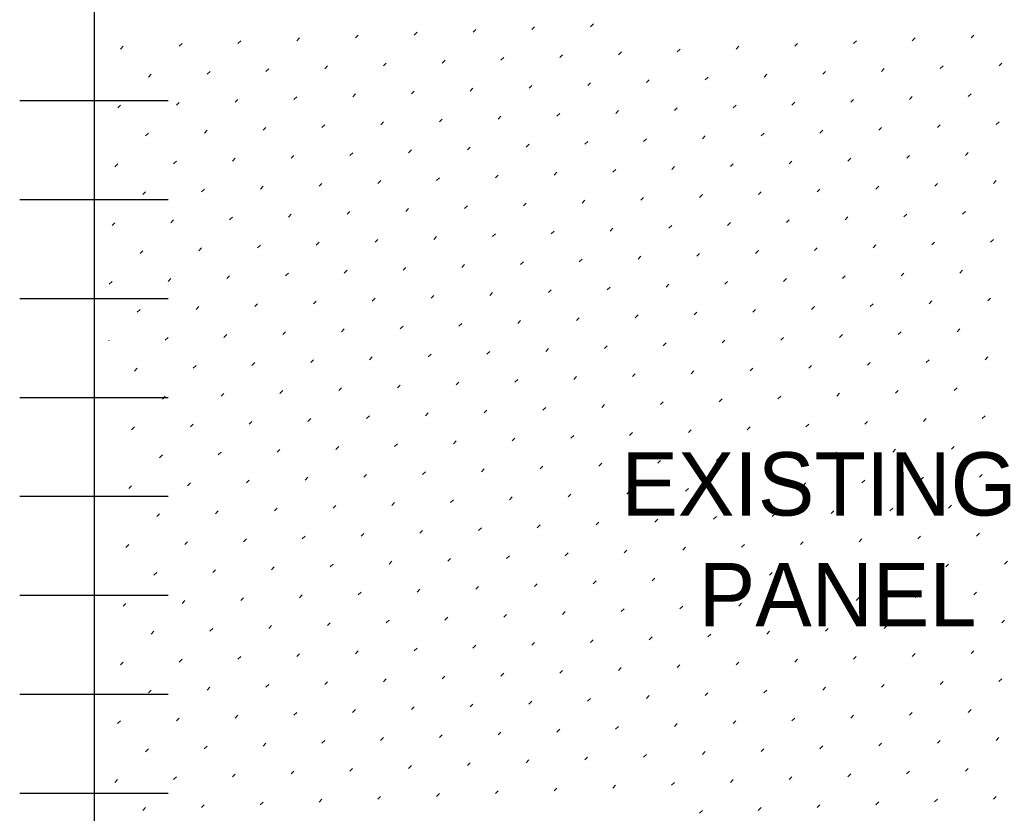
# Model space of a CAD drawing. Extents: x 49991.4 to 50021, y 49987.6 to 50011.4.
# Drawn here: x 50011.591 to 50012.843, y 49995.27 to 49996.272 of the extents above; entities that cross this region are included whole.
import ezdxf

# ---------------------------------------------------------------- set-up
doc = ezdxf.new("R2010")
doc.units = 0
for name, color, linetype in [('Level 1', 7, 'Continuous'), ('Level 10', 7, 'Continuous'), ('Level 2', 7, 'Continuous'), ('Level 4', 7, 'Continuous')]:
    doc.layers.add(name, color=color, linetype=linetype)

msp = doc.modelspace()

# ---------------------------------------------------------------- linework, layer by layer
at = {"layer": 'Level 1'}
msp.add_line((50011.6848, 49997.7903), (50011.6848, 49994.7903), dxfattribs=at)
at = {"layer": 'Level 10'}
for p, q in [((50012.238, 49996.2596), (50012.2415, 49996.2632)), ((50012.3123, 49996.2632), (50012.3158, 49996.2667)), ((50011.941, 49996.2454), (50011.9445, 49996.249)), ((50012.0152, 49996.249), (50012.0188, 49996.2525)), ((50012.0895, 49996.2525), (50012.093, 49996.2561)), ((50012.1638, 49996.2561), (50012.1673, 49996.2596)), ((50012.7189, 49996.2455), (50012.7224, 49996.2491)), ((50012.7931, 49996.2491), (50012.7967, 49996.2526)), ((50011.7182, 49996.2348), (50011.7218, 49996.2384)), ((50011.7925, 49996.2384), (50011.796, 49996.2419)), ((50011.8667, 49996.2419), (50011.8703, 49996.2454)), ((50012.4961, 49996.2349), (50012.4997, 49996.2384)), ((50012.5704, 49996.2384), (50012.5739, 49996.242)), ((50012.6446, 49996.242), (50012.6482, 49996.2455)), ((50012.1991, 49996.2207), (50012.2026, 49996.2243)), ((50012.2734, 49996.2243), (50012.2769, 49996.2278)), ((50012.3476, 49996.2278), (50012.3512, 49996.2313)), ((50012.4219, 49996.2313), (50012.4254, 49996.2349)), ((50011.9763, 49996.2101), (50011.9799, 49996.2136)), ((50012.0506, 49996.2136), (50012.0541, 49996.2172)), ((50012.1249, 49996.2172), (50012.1284, 49996.2207)), ((50012.7542, 49996.2102), (50012.7578, 49996.2137)), ((50012.8285, 49996.2137), (50012.832, 49996.2172)), ((50011.7536, 49996.1995), (50011.7571, 49996.203)), ((50011.8278, 49996.203), (50011.8314, 49996.2065)), ((50011.9021, 49996.2066), (50011.9056, 49996.2101)), ((50012.4572, 49996.196), (50012.4608, 49996.1995)), ((50012.5315, 49996.1995), (50012.535, 49996.2031)), ((50012.6057, 49996.2031), (50012.6093, 49996.2066)), ((50012.68, 49996.2066), (50012.6835, 49996.2102)), ((50012.2345, 49996.1854), (50012.238, 49996.1889)), ((50012.3087, 49996.1889), (50012.3123, 49996.1924)), ((50012.383, 49996.1925), (50012.3865, 49996.196)), ((50011.9375, 49996.1712), (50011.941, 49996.1747)), ((50012.0117, 49996.1747), (50012.0152, 49996.1783)), ((50012.086, 49996.1783), (50012.0895, 49996.1818)), ((50012.1602, 49996.1818), (50012.1637, 49996.1854)), ((50012.7153, 49996.1713), (50012.7189, 49996.1748)), ((50012.7896, 49996.1748), (50012.7931, 49996.1783)), ((50011.7147, 49996.1606), (50011.7182, 49996.1641)), ((50011.7889, 49996.1641), (50011.7925, 49996.1676)), ((50011.8632, 49996.1677), (50011.8667, 49996.1712)), ((50012.4183, 49996.1571), (50012.4219, 49996.1606)), ((50012.4926, 49996.1606), (50012.4961, 49996.1642)), ((50012.5668, 49996.1642), (50012.5704, 49996.1677)), ((50012.6411, 49996.1677), (50012.6446, 49996.1713)), ((50012.1956, 49996.1465), (50012.1991, 49996.15)), ((50012.2698, 49996.15), (50012.2734, 49996.1535)), ((50012.3441, 49996.1536), (50012.3476, 49996.1571)), ((50011.8986, 49996.1323), (50011.9021, 49996.1358)), ((50011.9728, 49996.1358), (50011.9763, 49996.1394)), ((50012.0471, 49996.1394), (50012.0506, 49996.1429)), ((50012.1213, 49996.1429), (50012.1248, 49996.1465)), ((50012.6764, 49996.1324), (50012.68, 49996.1359)), ((50012.7507, 49996.1359), (50012.7542, 49996.1394)), ((50012.8249, 49996.1395), (50012.8285, 49996.143)), ((50011.75, 49996.1252), (50011.7536, 49996.1287)), ((50011.8243, 49996.1288), (50011.8278, 49996.1323)), ((50012.4537, 49996.1217), (50012.4572, 49996.1253)), ((50012.5279, 49996.1253), (50012.5315, 49996.1288)), ((50012.6022, 49996.1288), (50012.6057, 49996.1324)), ((50012.1567, 49996.1076), (50012.1602, 49996.1111)), ((50012.2309, 49996.1111), (50012.2345, 49996.1146)), ((50012.3052, 49996.1147), (50012.3087, 49996.1182)), ((50012.3794, 49996.1182), (50012.383, 49996.1217)), ((50011.9339, 49996.0969), (50011.9374, 49996.1005)), ((50012.0082, 49996.1005), (50012.0117, 49996.104)), ((50012.0824, 49996.104), (50012.0859, 49996.1076)), ((50012.7118, 49996.097), (50012.7153, 49996.1005)), ((50012.786, 49996.1006), (50012.7896, 49996.1041)), ((50011.7111, 49996.0863), (50011.7147, 49996.0898)), ((50011.7854, 49996.0899), (50011.7889, 49996.0934)), ((50011.8597, 49996.0934), (50011.8632, 49996.0969)), ((50012.4148, 49996.0828), (50012.4183, 49996.0864)), ((50012.489, 49996.0864), (50012.4926, 49996.0899)), ((50012.5633, 49996.0899), (50012.5668, 49996.0935)), ((50012.6375, 49996.0935), (50012.6411, 49996.097)), ((50012.192, 49996.0722), (50012.1956, 49996.0758)), ((50012.2663, 49996.0758), (50012.2698, 49996.0793)), ((50012.3405, 49996.0793), (50012.3441, 49996.0828)), ((50011.895, 49996.058), (50011.8985, 49996.0616)), ((50011.9693, 49996.0616), (50011.9728, 49996.0651)), ((50012.0435, 49996.0651), (50012.0471, 49996.0687)), ((50012.1178, 49996.0687), (50012.1213, 49996.0722)), ((50012.6729, 49996.0581), (50012.6764, 49996.0617)), ((50012.7472, 49996.0617), (50012.7507, 49996.0652)), ((50012.8214, 49996.0652), (50012.8249, 49996.0687)), ((50011.7465, 49996.051), (50011.75, 49996.0545)), ((50011.8208, 49996.0545), (50011.8243, 49996.058)), ((50012.4501, 49996.0475), (50012.4537, 49996.051)), ((50012.5244, 49996.051), (50012.5279, 49996.0546)), ((50012.5986, 49996.0546), (50012.6022, 49996.0581)), ((50012.1531, 49996.0333), (50012.1567, 49996.0369)), ((50012.2274, 49996.0369), (50012.2309, 49996.0404)), ((50012.3016, 49996.0404), (50012.3052, 49996.0439)), ((50012.3759, 49996.0439), (50012.3794, 49996.0475)), ((50011.9304, 49996.0227), (50011.9339, 49996.0262)), ((50012.0046, 49996.0262), (50012.0082, 49996.0298)), ((50012.0789, 49996.0298), (50012.0824, 49996.0333)), ((50012.7083, 49996.0228), (50012.7118, 49996.0263)), ((50012.7825, 49996.0263), (50012.786, 49996.0298)), ((50011.7076, 49996.0121), (50011.7111, 49996.0156)), ((50011.7819, 49996.0156), (50011.7854, 49996.0191)), ((50011.8561, 49996.0191), (50011.8596, 49996.0227)), ((50012.4112, 49996.0086), (50012.4148, 49996.0121)), ((50012.4855, 49996.0121), (50012.489, 49996.0157)), ((50012.5597, 49996.0157), (50012.5633, 49996.0192)), ((50012.634, 49996.0192), (50012.6375, 49996.0228)), ((50012.1142, 49995.9944), (50012.1178, 49995.998)), ((50012.1885, 49995.998), (50012.192, 49996.0015)), ((50012.2627, 49996.0015), (50012.2663, 49996.005)), ((50012.337, 49996.005), (50012.3405, 49996.0086)), ((50011.8915, 49995.9838), (50011.895, 49995.9873)), ((50011.9657, 49995.9873), (50011.9693, 49995.9909)), ((50012.04, 49995.9909), (50012.0435, 49995.9944)), ((50012.6694, 49995.9839), (50012.6729, 49995.9874)), ((50012.7436, 49995.9874), (50012.7471, 49995.9909)), ((50012.8179, 49995.9909), (50012.8214, 49995.9945)), ((50011.743, 49995.9767), (50011.7465, 49995.9802)), ((50011.8172, 49995.9802), (50011.8207, 49995.9838)), ((50012.3723, 49995.9697), (50012.3759, 49995.9732)), ((50012.4466, 49995.9732), (50012.4501, 49995.9768)), ((50012.5208, 49995.9768), (50012.5244, 49995.9803)), ((50012.5951, 49995.9803), (50012.5986, 49995.9839)), ((50012.1496, 49995.9591), (50012.1531, 49995.9626)), ((50012.2238, 49995.9626), (50012.2274, 49995.9661)), ((50012.2981, 49995.9661), (50012.3016, 49995.9697)), ((50011.8526, 49995.9449), (50011.8561, 49995.9484)), ((50011.9268, 49995.9484), (50011.9304, 49995.952)), ((50012.0011, 49995.952), (50012.0046, 49995.9555)), ((50012.0753, 49995.9555), (50012.0789, 49995.9591)), ((50012.6305, 49995.945), (50012.634, 49995.9485)), ((50012.7047, 49995.9485), (50012.7082, 49995.952)), ((50012.779, 49995.952), (50012.7825, 49995.9556)), ((50011.7041, 49995.9378), (50011.7076, 49995.9413)), ((50011.7783, 49995.9414), (50011.7819, 49995.9449)), ((50012.4077, 49995.9343), (50012.4112, 49995.9379)), ((50012.482, 49995.9379), (50012.4855, 49995.9414)), ((50012.5562, 49995.9414), (50012.5597, 49995.945)), ((50012.1107, 49995.9202), (50012.1142, 49995.9237)), ((50012.1849, 49995.9237), (50012.1885, 49995.9272)), ((50012.2592, 49995.9273), (50012.2627, 49995.9308)), ((50012.3334, 49995.9308), (50012.337, 49995.9343)), ((50011.8879, 49995.9095), (50011.8915, 49995.9131)), ((50011.9622, 49995.9131), (50011.9657, 49995.9166)), ((50012.0364, 49995.9166), (50012.04, 49995.9202)), ((50012.6658, 49995.9096), (50012.6693, 49995.9131)), ((50012.7401, 49995.9132), (50012.7436, 49995.9167)), ((50012.8143, 49995.9167), (50012.8179, 49995.9202)), ((50011.7394, 49995.9025), (50011.743, 49995.906)), ((50011.8137, 49995.906), (50011.8172, 49995.9095)), ((50012.3688, 49995.8954), (50012.3723, 49995.899)), ((50012.4431, 49995.899), (50012.4466, 49995.9025)), ((50012.5173, 49995.9025), (50012.5208, 49995.9061)), ((50012.5916, 49995.9061), (50012.5951, 49995.9096)), ((50012.146, 49995.8848), (50012.1496, 49995.8883)), ((50012.2203, 49995.8884), (50012.2238, 49995.8919)), ((50012.2945, 49995.8919), (50012.2981, 49995.8954)), ((50011.849, 49995.8706), (50011.8526, 49995.8742)), ((50011.9233, 49995.8742), (50011.9268, 49995.8777)), ((50011.9975, 49995.8777), (50012.0011, 49995.8813)), ((50012.0718, 49995.8813), (50012.0753, 49995.8848)), ((50012.6269, 49995.8707), (50012.6305, 49995.8742)), ((50012.7012, 49995.8743), (50012.7047, 49995.8778)), ((50012.7754, 49995.8778), (50012.779, 49995.8813)), ((50011.7038, 49995.8668), (50011.7041, 49995.8671)), ((50011.7748, 49995.8671), (50011.7783, 49995.8706)), ((50012.4042, 49995.8601), (50012.4077, 49995.8636)), ((50012.4784, 49995.8636), (50012.4819, 49995.8672)), ((50012.5527, 49995.8672), (50012.5562, 49995.8707)), ((50012.1071, 49995.8459), (50012.1107, 49995.8494)), ((50012.1814, 49995.8495), (50012.1849, 49995.853)), ((50012.2556, 49995.853), (50012.2592, 49995.8565)), ((50012.3299, 49995.8565), (50012.3334, 49995.8601)), ((50011.8101, 49995.8317), (50011.8137, 49995.8353)), ((50011.8844, 49995.8353), (50011.8879, 49995.8388)), ((50011.9586, 49995.8388), (50011.9622, 49995.8424)), ((50012.0329, 49995.8424), (50012.0364, 49995.8459)), ((50012.588, 49995.8318), (50012.5916, 49995.8353)), ((50012.6623, 49995.8354), (50012.6658, 49995.8389)), ((50012.7365, 49995.8389), (50012.7401, 49995.8424)), ((50012.8108, 49995.8424), (50012.8143, 49995.846)), ((50011.7359, 49995.8282), (50011.7394, 49995.8317)), ((50012.3653, 49995.8212), (50012.3688, 49995.8247)), ((50012.4395, 49995.8247), (50012.443, 49995.8283)), ((50012.5138, 49995.8283), (50012.5173, 49995.8318)), ((50012.0682, 49995.807), (50012.0718, 49995.8105)), ((50012.1425, 49995.8106), (50012.146, 49995.8141)), ((50012.2168, 49995.8141), (50012.2203, 49995.8176)), ((50012.291, 49995.8176), (50012.2945, 49995.8212)), ((50011.8455, 49995.7964), (50011.849, 49995.7999)), ((50011.9197, 49995.7999), (50011.9233, 49995.8035)), ((50011.994, 49995.8035), (50011.9975, 49995.807)), ((50012.6234, 49995.7965), (50012.6269, 49995.8)), ((50012.6976, 49995.8), (50012.7012, 49995.8035)), ((50012.7719, 49995.8035), (50012.7754, 49995.8071)), ((50011.7712, 49995.7928), (50011.7748, 49995.7964)), ((50012.3264, 49995.7823), (50012.3299, 49995.7858)), ((50012.4006, 49995.7858), (50012.4041, 49995.7894)), ((50012.4749, 49995.7894), (50012.4784, 49995.7929)), ((50012.5491, 49995.7929), (50012.5527, 49995.7965)), ((50012.1036, 49995.7717), (50012.1071, 49995.7752)), ((50012.1779, 49995.7752), (50012.1814, 49995.7787)), ((50012.2521, 49995.7787), (50012.2556, 49995.7823)), ((50011.8066, 49995.7575), (50011.8101, 49995.761)), ((50011.8808, 49995.761), (50011.8844, 49995.7646)), ((50011.9551, 49995.7646), (50011.9586, 49995.7681)), ((50012.0293, 49995.7681), (50012.0329, 49995.7717)), ((50012.5845, 49995.7576), (50012.588, 49995.7611)), ((50012.6587, 49995.7611), (50012.6623, 49995.7646)), ((50012.733, 49995.7646), (50012.7365, 49995.7682)), ((50012.8072, 49995.7682), (50012.8108, 49995.7717)), ((50011.7323, 49995.7539), (50011.7359, 49995.7575)), ((50012.3617, 49995.7469), (50012.3653, 49995.7505)), ((50012.436, 49995.7505), (50012.4395, 49995.754)), ((50012.5102, 49995.754), (50012.5138, 49995.7576)), ((50012.0647, 49995.7328), (50012.0682, 49995.7363)), ((50012.139, 49995.7363), (50012.1425, 49995.7398)), ((50012.2132, 49995.7398), (50012.2167, 49995.7434)), ((50012.2875, 49995.7434), (50012.291, 49995.7469)), ((50011.8419, 49995.7221), (50011.8455, 49995.7257)), ((50011.9162, 49995.7257), (50011.9197, 49995.7292)), ((50011.9904, 49995.7292), (50011.994, 49995.7328)), ((50012.6198, 49995.7222), (50012.6234, 49995.7257)), ((50012.6941, 49995.7257), (50012.6976, 49995.7293)), ((50012.7683, 49995.7293), (50012.7719, 49995.7328)), ((50011.7677, 49995.7186), (50011.7712, 49995.7221)), ((50012.3228, 49995.708), (50012.3264, 49995.7116)), ((50012.3971, 49995.7116), (50012.4006, 49995.7151)), ((50012.4713, 49995.7151), (50012.4749, 49995.7187)), ((50012.5456, 49995.7187), (50012.5491, 49995.7222)), ((50012.1001, 49995.6974), (50012.1036, 49995.7009)), ((50012.1743, 49995.7009), (50012.1778, 49995.7045)), ((50012.2486, 49995.7045), (50012.2521, 49995.708)), ((50011.803, 49995.6832), (50011.8066, 49995.6868)), ((50011.8773, 49995.6868), (50011.8808, 49995.6903)), ((50011.9516, 49995.6903), (50011.9551, 49995.6939)), ((50012.0258, 49995.6939), (50012.0293, 49995.6974)), ((50012.5809, 49995.6833), (50012.5845, 49995.6868)), ((50012.6552, 49995.6868), (50012.6587, 49995.6904)), ((50012.7294, 49995.6904), (50012.733, 49995.6939)), ((50012.8037, 49995.6939), (50012.8072, 49995.6975)), ((50011.7288, 49995.6797), (50011.7323, 49995.6832)), ((50012.2839, 49995.6691), (50012.2875, 49995.6727)), ((50012.3582, 49995.6727), (50012.3617, 49995.6762)), ((50012.4324, 49995.6762), (50012.436, 49995.6798)), ((50012.5067, 49995.6798), (50012.5102, 49995.6833)), ((50012.0612, 49995.6585), (50012.0647, 49995.662)), ((50012.1354, 49995.6621), (50012.1389, 49995.6656)), ((50012.2097, 49995.6656), (50012.2132, 49995.6691)), ((50012.839, 49995.6586), (50012.8426, 49995.6621)), ((50011.7641, 49995.6443), (50011.7677, 49995.6479)), ((50011.8384, 49995.6479), (50011.8419, 49995.6514)), ((50011.9127, 49995.6514), (50011.9162, 49995.655)), ((50011.9869, 49995.655), (50011.9904, 49995.6585)), ((50012.542, 49995.6444), (50012.5456, 49995.6479)), ((50012.6163, 49995.648), (50012.6198, 49995.6515)), ((50012.6905, 49995.6515), (50012.6941, 49995.655)), ((50012.7648, 49995.655), (50012.7683, 49995.6586)), ((50012.3193, 49995.6338), (50012.3228, 49995.6373)), ((50012.3935, 49995.6373), (50012.3971, 49995.6409)), ((50012.4678, 49995.6409), (50012.4713, 49995.6444)), ((50012.0223, 49995.6196), (50012.0258, 49995.6231)), ((50012.0965, 49995.6232), (50012.1, 49995.6267)), ((50012.1708, 49995.6267), (50012.1743, 49995.6302)), ((50012.245, 49995.6302), (50012.2486, 49995.6338)), ((50012.8001, 49995.6197), (50012.8037, 49995.6232)), ((50011.7995, 49995.609), (50011.803, 49995.6125)), ((50011.8738, 49995.6125), (50011.8773, 49995.6161)), ((50011.948, 49995.6161), (50011.9515, 49995.6196)), ((50012.5774, 49995.6091), (50012.5809, 49995.6126)), ((50012.6516, 49995.6126), (50012.6552, 49995.6161)), ((50012.7259, 49995.6161), (50012.7294, 49995.6197)), ((50011.7252, 49995.6054), (50011.7288, 49995.609)), ((50012.2804, 49995.5949), (50012.2839, 49995.5984)), ((50012.3546, 49995.5984), (50012.3582, 49995.602)), ((50012.4289, 49995.602), (50012.4324, 49995.6055)), ((50012.5031, 49995.6055), (50012.5067, 49995.609)), ((50012.0576, 49995.5843), (50012.0612, 49995.5878)), ((50012.1319, 49995.5878), (50012.1354, 49995.5913)), ((50012.2061, 49995.5913), (50012.2097, 49995.5949)), ((50012.8355, 49995.5843), (50012.839, 49995.5879)), ((50011.7606, 49995.5701), (50011.7641, 49995.5736)), ((50011.8349, 49995.5736), (50011.8384, 49995.5772)), ((50011.9091, 49995.5772), (50011.9126, 49995.5807)), ((50011.9834, 49995.5807), (50011.9869, 49995.5842)), ((50012.5385, 49995.5702), (50012.542, 49995.5737)), ((50012.6127, 49995.5737), (50012.6163, 49995.5772)), ((50012.687, 49995.5772), (50012.6905, 49995.5808)), ((50012.7613, 49995.5808), (50012.7648, 49995.5843)), ((50012.3157, 49995.5595), (50012.3193, 49995.5631)), ((50012.39, 49995.5631), (50012.3935, 49995.5666)), ((50012.4642, 49995.5666), (50012.4678, 49995.5701)), ((50012.0187, 49995.5454), (50012.0223, 49995.5489)), ((50012.093, 49995.5489), (50012.0965, 49995.5524)), ((50012.1672, 49995.5524), (50012.1708, 49995.556)), ((50012.2415, 49995.556), (50012.245, 49995.5595)), ((50012.7966, 49995.5454), (50012.8001, 49995.549)), ((50011.796, 49995.5347), (50011.7995, 49995.5383)), ((50011.8702, 49995.5383), (50011.8737, 49995.5418)), ((50011.9445, 49995.5418), (50011.948, 49995.5453)), ((50012.4996, 49995.5313), (50012.5031, 49995.5348)), ((50012.5738, 49995.5348), (50012.5774, 49995.5383)), ((50012.6481, 49995.5383), (50012.6516, 49995.5419)), ((50012.7224, 49995.5419), (50012.7259, 49995.5454)), ((50011.7217, 49995.5312), (50011.7252, 49995.5347)), ((50012.2768, 49995.5206), (50012.2804, 49995.5242)), ((50012.3511, 49995.5242), (50012.3546, 49995.5277)), ((50012.4253, 49995.5277), (50012.4289, 49995.5312)), ((50011.9798, 49995.5065), (50011.9834, 49995.51)), ((50012.0541, 49995.51), (50012.0576, 49995.5135)), ((50012.1283, 49995.5135), (50012.1319, 49995.5171)), ((50012.2026, 49995.5171), (50012.2061, 49995.5206)), ((50012.7577, 49995.5065), (50012.7612, 49995.5101)), ((50012.832, 49995.5101), (50012.8355, 49995.5136)), ((50011.7571, 49995.4958), (50011.7606, 49995.4994)), ((50011.8313, 49995.4994), (50011.8348, 49995.5029)), ((50011.9056, 49995.5029), (50011.9091, 49995.5065)), ((50012.5349, 49995.4959), (50012.5385, 49995.4994)), ((50012.6092, 49995.4994), (50012.6127, 49995.503)), ((50012.6835, 49995.503), (50012.687, 49995.5065)), ((50012.2379, 49995.4817), (50012.2415, 49995.4853)), ((50012.3122, 49995.4853), (50012.3157, 49995.4888)), ((50012.3864, 49995.4888), (50012.39, 49995.4924)), ((50012.4607, 49995.4924), (50012.4642, 49995.4959)), ((50012.0152, 49995.4711), (50012.0187, 49995.4746)), ((50012.0894, 49995.4746), (50012.093, 49995.4782)), ((50012.1637, 49995.4782), (50012.1672, 49995.4817)), ((50012.7931, 49995.4712), (50012.7966, 49995.4747)), ((50011.7182, 49995.4569), (50011.7217, 49995.4605)), ((50011.7924, 49995.4605), (50011.796, 49995.464)), ((50011.8667, 49995.464), (50011.8702, 49995.4676)), ((50011.9409, 49995.4676), (50011.9445, 49995.4711)), ((50012.4961, 49995.457), (50012.4996, 49995.4605)), ((50012.5703, 49995.4605), (50012.5738, 49995.4641)), ((50012.6446, 49995.4641), (50012.6481, 49995.4676)), ((50012.7188, 49995.4676), (50012.7223, 49995.4712)), ((50012.2733, 49995.4464), (50012.2768, 49995.4499)), ((50012.3475, 49995.4499), (50012.3511, 49995.4535)), ((50012.4218, 49995.4535), (50012.4253, 49995.457)), ((50011.9763, 49995.4322), (50011.9798, 49995.4357)), ((50012.0505, 49995.4357), (50012.0541, 49995.4393)), ((50012.1248, 49995.4393), (50012.1283, 49995.4428)), ((50012.199, 49995.4428), (50012.2026, 49995.4464)), ((50012.7542, 49995.4323), (50012.7577, 49995.4358)), ((50012.8284, 49995.4358), (50012.832, 49995.4394)), ((50011.7535, 49995.4216), (50011.7571, 49995.4251)), ((50011.8278, 49995.4251), (50011.8313, 49995.4287)), ((50011.902, 49995.4287), (50011.9056, 49995.4322)), ((50012.5314, 49995.4216), (50012.5349, 49995.4252)), ((50012.6057, 49995.4252), (50012.6092, 49995.4287)), ((50012.6799, 49995.4287), (50012.6834, 49995.4323)), ((50012.2344, 49995.4075), (50012.2379, 49995.411)), ((50012.3086, 49995.411), (50012.3122, 49995.4146)), ((50012.3829, 49995.4146), (50012.3864, 49995.4181)), ((50012.4572, 49995.4181), (50012.4607, 49995.4216)), ((50012.0116, 49995.3968), (50012.0152, 49995.4004)), ((50012.0859, 49995.4004), (50012.0894, 49995.4039)), ((50012.1601, 49995.4039), (50012.1637, 49995.4075)), ((50012.7895, 49995.3969), (50012.7931, 49995.4005)), ((50011.7146, 49995.3827), (50011.7182, 49995.3862)), ((50011.7889, 49995.3862), (50011.7924, 49995.3898)), ((50011.8631, 49995.3898), (50011.8667, 49995.3933)), ((50011.9374, 49995.3933), (50011.9409, 49995.3968)), ((50012.4925, 49995.3828), (50012.496, 49995.3863)), ((50012.5668, 49995.3863), (50012.5703, 49995.3898)), ((50012.641, 49995.3898), (50012.6446, 49995.3934)), ((50012.7153, 49995.3934), (50012.7188, 49995.3969)), ((50012.1955, 49995.3686), (50012.199, 49995.3721)), ((50012.2697, 49995.3721), (50012.2733, 49995.3757)), ((50012.344, 49995.3757), (50012.3475, 49995.3792)), ((50012.4183, 49995.3792), (50012.4218, 49995.3827)), ((50011.9727, 49995.358), (50011.9763, 49995.3615)), ((50012.047, 49995.3615), (50012.0505, 49995.365)), ((50012.1212, 49995.365), (50012.1248, 49995.3686)), ((50012.7506, 49995.358), (50012.7542, 49995.3616)), ((50012.8249, 49995.3616), (50012.8284, 49995.3651)), ((50011.75, 49995.3473), (50011.7535, 49995.3509)), ((50011.8242, 49995.3509), (50011.8278, 49995.3544)), ((50011.8985, 49995.3544), (50011.902, 49995.3579)), ((50012.4536, 49995.3439), (50012.4571, 49995.3474)), ((50012.5279, 49995.3474), (50012.5314, 49995.3509)), ((50012.6021, 49995.3509), (50012.6057, 49995.3545)), ((50012.6764, 49995.3545), (50012.6799, 49995.358)), ((50012.2309, 49995.3332), (50012.2344, 49995.3368)), ((50012.3051, 49995.3368), (50012.3086, 49995.3403)), ((50012.3794, 49995.3403), (50012.3829, 49995.3438)), ((50011.9338, 49995.3191), (50011.9374, 49995.3226)), ((50012.0081, 49995.3226), (50012.0116, 49995.3261)), ((50012.0823, 49995.3261), (50012.0859, 49995.3297)), ((50012.1566, 49995.3297), (50012.1601, 49995.3332)), ((50012.7117, 49995.3191), (50012.7153, 49995.3227)), ((50012.786, 49995.3227), (50012.7895, 49995.3262)), ((50011.7111, 49995.3084), (50011.7146, 49995.312)), ((50011.7853, 49995.312), (50011.7889, 49995.3155)), ((50011.8596, 49995.3155), (50011.8631, 49995.319)), ((50012.489, 49995.3085), (50012.4925, 49995.312)), ((50012.5632, 49995.312), (50012.5668, 49995.3156)), ((50012.6375, 49995.3156), (50012.641, 49995.3191)), ((50012.192, 49995.2943), (50012.1955, 49995.2979)), ((50012.2662, 49995.2979), (50012.2697, 49995.3014)), ((50012.3405, 49995.3014), (50012.344, 49995.3049)), ((50012.4147, 49995.305), (50012.4182, 49995.3085)), ((50011.9692, 49995.2837), (50011.9727, 49995.2872)), ((50012.0434, 49995.2872), (50012.047, 49995.2908)), ((50012.1177, 49995.2908), (50012.1212, 49995.2943)), ((50012.7471, 49995.2838), (50012.7506, 49995.2873)), ((50012.8213, 49995.2873), (50012.8249, 49995.2908)), ((50011.7464, 49995.2731), (50011.75, 49995.2766)), ((50011.8207, 49995.2766), (50011.8242, 49995.2801)), ((50011.8949, 49995.2802), (50011.8985, 49995.2837)), ((50012.4501, 49995.2696), (50012.4536, 49995.2731)), ((50012.5243, 49995.2731), (50012.5279, 49995.2767)), ((50012.5986, 49995.2767), (50012.6021, 49995.2802)), ((50012.6728, 49995.2802), (50012.6764, 49995.2838))]:
    msp.add_line(p, q, dxfattribs=at)
at = {"layer": 'Level 4'}
for p, q in [((50011.7785, 49996.1695), (50011.591, 49996.1695)), ((50011.7785, 49996.0445), (50011.591, 49996.0445)), ((50011.7785, 49995.9195), (50011.591, 49995.9195)), ((50011.7785, 49995.7945), (50011.591, 49995.7945)), ((50011.7785, 49995.6695), (50011.591, 49995.6695)), ((50011.7785, 49995.5445), (50011.591, 49995.5445)), ((50011.7785, 49995.4195), (50011.591, 49995.4195)), ((50011.7785, 49995.2945), (50011.591, 49995.2945))]:
    msp.add_line(p, q, dxfattribs=at)

# ---------------------------------------------------------------- texts
at = {"layer": 'Level 2'}
for s, p in [('EXISTING', (50012.3513, 49995.6456)), ('PANEL', (50012.4491, 49995.5056))]:
    msp.add_text(s, height=0.08, dxfattribs=at).set_placement(p)

doc.saveas('drawing.dxf')
